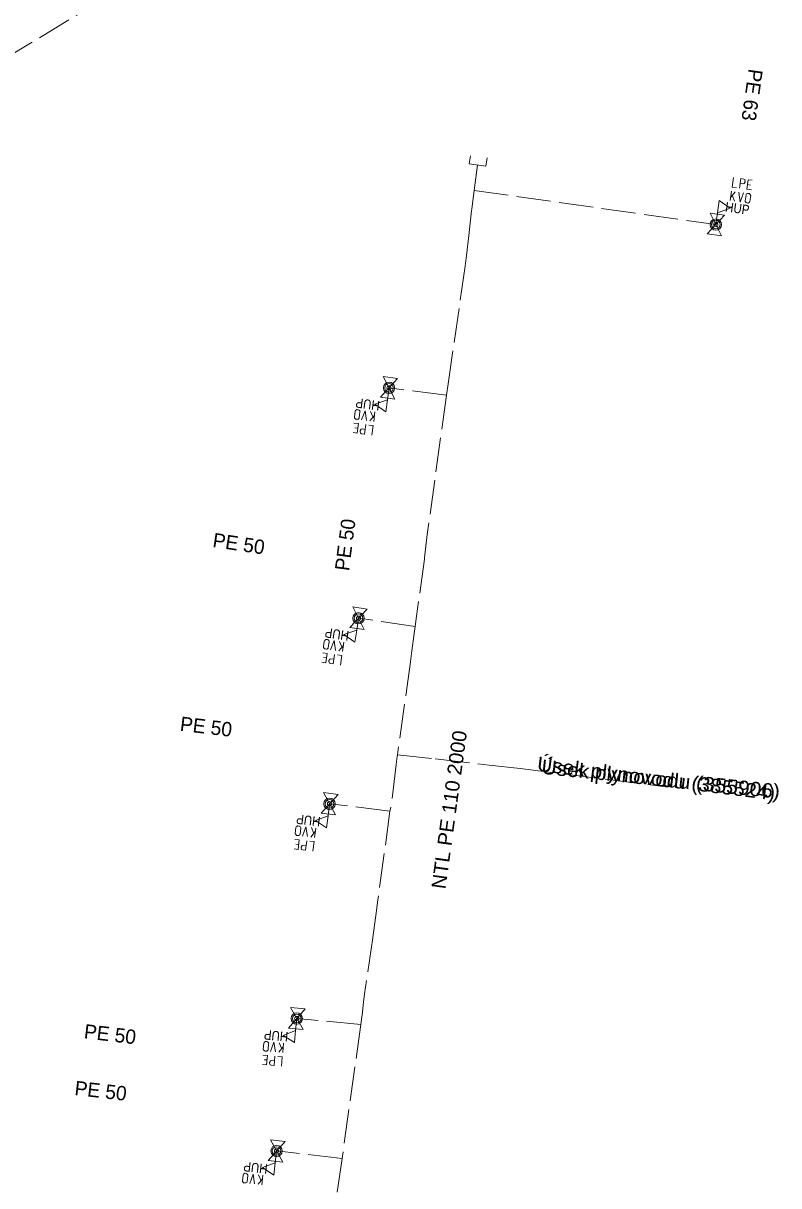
# Model space of a CAD drawing. Extents: x -688140 to -687678, y -1056859 to -1056384.
# Drawn here: x -687935 to -687895.3, y -1056552.8 to -1056491.8 of the extents above; entities that cross this region are included whole.
import ezdxf
from ezdxf.enums import TextEntityAlignment as Align

# ---------------------------------------------------------------- set-up
doc = ezdxf.new("R2010")
doc.units = 0
doc.header["$LTSCALE"] = 0.3
doc.linetypes.add('LONG_DASHED', pattern=[7.5, 6, -1.5])
for name, color, linetype, lineweight in [('12', 7, 'Continuous', 13), ('35', 7, 'LONG_DASHED', 13), ('50', 7, 'LONG_DASHED', 13)]:
    doc.layers.add(name, color=color, linetype=linetype, lineweight=lineweight)
doc.layers.add('15', color=7, linetype='Continuous')

msp = doc.modelspace()

# ---------------------------------------------------------------- linework, layer by layer
at = {"layer": '12'}
for p, q in [((-687897.187, -1056500.239), (-687897.345, -1056500.217)), ((-687896.802, -1056500.304), (-687896.96, -1056500.281)), ((-687897.797, -1056500.628), (-687897.867, -1056501.123)), ((-687897.84, -1056500.935), (-687897.599, -1056500.656)), ((-687897.766, -1056500.834), (-687897.639, -1056501.155)), ((-687897.081, -1056501.133), (-687897.037, -1056500.826)), ((-687896.79, -1056500.861), (-687896.833, -1056501.168)), ((-687898.163, -1056501.894), (-687899.077, -1056502.866)), ((-687898.925, -1056501.787), (-687898.315, -1056502.973)), ((-687898.925, -1056501.787), (-687898.163, -1056501.894)), ((-687898.62, -1056502.38), (-687898.532, -1056501.756)), ((-687899.077, -1056502.866), (-687898.315, -1056502.973)), ((-687916.222, -1056511.441), (-687915.318, -1056510.459)), ((-687915.318, -1056510.459), (-687916.082, -1056510.36)), ((-687915.458, -1056511.54), (-687916.082, -1056510.36)), ((-687915.77, -1056510.95), (-687915.851, -1056511.575)), ((-687915.458, -1056511.54), (-687916.222, -1056511.441)), ((-687917.583, -1056512.49), (-687917.543, -1056512.182)), ((-687917.295, -1056512.214), (-687917.335, -1056512.522)), ((-687916.533, -1056512.404), (-687916.771, -1056512.686)), ((-687916.607, -1056512.505), (-687916.737, -1056512.186)), ((-687916.573, -1056512.711), (-687916.509, -1056512.216)), ((-687917.564, -1056513.047), (-687917.406, -1056513.067)), ((-687917.179, -1056513.107), (-687917.02, -1056513.127)), ((-687917.831, -1056523.523), (-687916.909, -1056522.557)), ((-687916.909, -1056522.557), (-687917.671, -1056522.444)), ((-687917.069, -1056523.636), (-687917.671, -1056522.444)), ((-687917.069, -1056523.636), (-687917.831, -1056523.523)), ((-687917.37, -1056523.04), (-687917.462, -1056523.663)), ((-687919.211, -1056524.546), (-687919.165, -1056524.24)), ((-687918.918, -1056524.276), (-687918.963, -1056524.583)), ((-687918.16, -1056524.48), (-687918.403, -1056524.757)), ((-687918.235, -1056524.58), (-687918.359, -1056524.258)), ((-687918.205, -1056524.786), (-687918.132, -1056524.292)), ((-687919.202, -1056525.104), (-687919.044, -1056525.127)), ((-687918.818, -1056525.171), (-687918.66, -1056525.194)), ((-687919.337, -1056533.275), (-687918.443, -1056532.285)), ((-687918.443, -1056532.285), (-687919.207, -1056532.193)), ((-687918.573, -1056533.367), (-687919.207, -1056532.193)), ((-687918.573, -1056533.367), (-687919.337, -1056533.275)), ((-687918.89, -1056532.78), (-687918.965, -1056533.406)), ((-687920.688, -1056534.337), (-687920.651, -1056534.029)), ((-687920.403, -1056534.059), (-687920.44, -1056534.367)), ((-687919.639, -1056534.241), (-687919.875, -1056534.525)), ((-687919.712, -1056534.343), (-687919.845, -1056534.025)), ((-687919.676, -1056534.549), (-687919.617, -1056534.053)), ((-687920.664, -1056534.894), (-687920.505, -1056534.913)), ((-687920.278, -1056534.95), (-687920.119, -1056534.969)), ((-687921.043, -1056544.557), (-687920.177, -1056543.543)), ((-687920.177, -1056543.543), (-687920.943, -1056543.472)), ((-687920.277, -1056544.628), (-687920.943, -1056543.472)), ((-687920.61, -1056544.05), (-687920.668, -1056544.677)), ((-687920.277, -1056544.628), (-687921.043, -1056544.557)), ((-687922.365, -1056545.656), (-687922.336, -1056545.347)), ((-687922.087, -1056545.37), (-687922.116, -1056545.679)), ((-687921.319, -1056545.531), (-687921.547, -1056545.821)), ((-687921.389, -1056545.635), (-687921.531, -1056545.321)), ((-687921.348, -1056545.84), (-687921.302, -1056545.342)), ((-687922.326, -1056546.212), (-687922.166, -1056546.226)), ((-687921.938, -1056546.257), (-687921.779, -1056546.272)), ((-687921.226, -1056550.502), (-687921.991, -1056550.415)), ((-687921.349, -1056551.585), (-687921.991, -1056550.415)), ((-687922.114, -1056551.498), (-687921.226, -1056550.502)), ((-687921.67, -1056551), (-687921.741, -1056551.626)), ((-687921.349, -1056551.585), (-687922.114, -1056551.498)), ((-687923.458, -1056552.569), (-687923.423, -1056552.261)), ((-687923.175, -1056552.289), (-687923.21, -1056552.597)), ((-687922.482, -1056552.569), (-687922.617, -1056552.251)), ((-687922.445, -1056552.774), (-687922.388, -1056552.277)), ((-687922.41, -1056552.466), (-687922.644, -1056552.751))]:
    msp.add_line(p, q, dxfattribs=at)
for points in [[(-687910.624, -1056498.882), (-687910.683, -1056499.319), (-687911.557, -1056499.201), (-687911.498, -1056498.764)], [(-687897.696, -1056499.915), (-687897.766, -1056500.41), (-687897.539, -1056500.442)], [(-687897.38, -1056500.464), (-687897.31, -1056499.969), (-687897.152, -1056499.992)], [(-687897.152, -1056499.992), (-687897.105, -1056500.019), (-687897.077, -1056500.103), (-687897.082, -1056500.143), (-687897.134, -1056500.226), (-687897.187, -1056500.239)], [(-687896.706, -1056500.055), (-687896.924, -1056500.024), (-687896.994, -1056500.519), (-687896.756, -1056500.552)], [(-687897.421, -1056500.681), (-687897.352, -1056501.196), (-687897.163, -1056500.717)], [(-687897.037, -1056500.826), (-687897.033, -1056500.796), (-687897.009, -1056500.769), (-687896.965, -1056500.745), (-687896.926, -1056500.751), (-687896.876, -1056500.758), (-687896.846, -1056500.762), (-687896.812, -1056500.807), (-687896.795, -1056500.83), (-687896.79, -1056500.861)], [(-687897.081, -1056501.133), (-687897.086, -1056501.172), (-687897.069, -1056501.195), (-687897.034, -1056501.23), (-687896.996, -1056501.246), (-687896.946, -1056501.253), (-687896.916, -1056501.257), (-687896.871, -1056501.223), (-687896.849, -1056501.206), (-687896.833, -1056501.168)], [(-687917.335, -1056512.522), (-687917.339, -1056512.552), (-687917.363, -1056512.579), (-687917.406, -1056512.603), (-687917.446, -1056512.598), (-687917.495, -1056512.592), (-687917.525, -1056512.588), (-687917.56, -1056512.543), (-687917.577, -1056512.521), (-687917.583, -1056512.49)], [(-687917.295, -1056512.214), (-687917.29, -1056512.175), (-687917.307, -1056512.152), (-687917.343, -1056512.117), (-687917.381, -1056512.102), (-687917.431, -1056512.096), (-687917.461, -1056512.092), (-687917.506, -1056512.127), (-687917.528, -1056512.144), (-687917.543, -1056512.182)], [(-687916.95, -1056512.663), (-687917.024, -1056512.149), (-687917.208, -1056512.629)], [(-687917.657, -1056513.297), (-687917.439, -1056513.325), (-687917.375, -1056512.829), (-687917.613, -1056512.798)], [(-687917.211, -1056513.355), (-687917.258, -1056513.328), (-687917.287, -1056513.244), (-687917.282, -1056513.204), (-687917.231, -1056513.12), (-687917.179, -1056513.107)], [(-687916.988, -1056512.879), (-687917.052, -1056513.375), (-687917.211, -1056513.355)], [(-687916.666, -1056513.425), (-687916.601, -1056512.93), (-687916.829, -1056512.9)], [(-687918.918, -1056524.276), (-687918.912, -1056524.237), (-687918.929, -1056524.214), (-687918.964, -1056524.179), (-687919.002, -1056524.163), (-687919.052, -1056524.156), (-687919.081, -1056524.151), (-687919.127, -1056524.185), (-687919.149, -1056524.202), (-687919.165, -1056524.24)], [(-687918.581, -1056524.731), (-687918.646, -1056524.216), (-687918.838, -1056524.693)], [(-687918.963, -1056524.583), (-687918.968, -1056524.613), (-687918.992, -1056524.64), (-687919.036, -1056524.663), (-687919.075, -1056524.658), (-687919.125, -1056524.65), (-687919.155, -1056524.646), (-687919.188, -1056524.6), (-687919.205, -1056524.578), (-687919.211, -1056524.546)], [(-687919.3, -1056525.352), (-687919.082, -1056525.384), (-687919.009, -1056524.89), (-687919.246, -1056524.855)], [(-687918.855, -1056525.418), (-687918.901, -1056525.391), (-687918.929, -1056525.306), (-687918.923, -1056525.266), (-687918.87, -1056525.183), (-687918.818, -1056525.171)], [(-687918.623, -1056524.947), (-687918.696, -1056525.442), (-687918.855, -1056525.418)], [(-687918.311, -1056525.499), (-687918.237, -1056525.004), (-687918.465, -1056524.97)], [(-687920.403, -1056534.059), (-687920.398, -1056534.019), (-687920.416, -1056533.997), (-687920.452, -1056533.963), (-687920.49, -1056533.948), (-687920.54, -1056533.942), (-687920.57, -1056533.938), (-687920.614, -1056533.973), (-687920.637, -1056533.991), (-687920.651, -1056534.029)], [(-687920.44, -1056534.367), (-687920.443, -1056534.397), (-687920.467, -1056534.424), (-687920.51, -1056534.449), (-687920.55, -1056534.444), (-687920.6, -1056534.438), (-687920.629, -1056534.435), (-687920.664, -1056534.39), (-687920.682, -1056534.368), (-687920.688, -1056534.337)], [(-687920.053, -1056534.504), (-687920.133, -1056533.991), (-687920.312, -1056534.473)], [(-687920.755, -1056535.145), (-687920.536, -1056535.171), (-687920.477, -1056534.675), (-687920.715, -1056534.646)], [(-687920.308, -1056535.198), (-687920.355, -1056535.173), (-687920.385, -1056535.088), (-687920.381, -1056535.049), (-687920.33, -1056534.964), (-687920.278, -1056534.95)], [(-687920.09, -1056534.721), (-687920.149, -1056535.217), (-687920.308, -1056535.198)], [(-687919.762, -1056535.264), (-687919.702, -1056534.767), (-687919.931, -1056534.74)], [(-687922.087, -1056545.37), (-687922.084, -1056545.33), (-687922.102, -1056545.308), (-687922.139, -1056545.275), (-687922.178, -1056545.261), (-687922.228, -1056545.257), (-687922.258, -1056545.254), (-687922.301, -1056545.29), (-687922.323, -1056545.308), (-687922.336, -1056545.347)], [(-687921.726, -1056545.805), (-687921.819, -1056545.294), (-687921.985, -1056545.781)], [(-687922.409, -1056546.465), (-687922.19, -1056546.485), (-687922.144, -1056545.987), (-687922.383, -1056545.965)], [(-687922.116, -1056545.679), (-687922.119, -1056545.708), (-687922.141, -1056545.736), (-687922.184, -1056545.763), (-687922.224, -1056545.759), (-687922.274, -1056545.754), (-687922.303, -1056545.752), (-687922.34, -1056545.708), (-687922.358, -1056545.686), (-687922.365, -1056545.656)], [(-687921.756, -1056546.023), (-687921.802, -1056546.521), (-687921.961, -1056546.506)], [(-687921.414, -1056546.557), (-687921.368, -1056546.059), (-687921.597, -1056546.038)], [(-687921.961, -1056546.506), (-687922.009, -1056546.482), (-687922.042, -1056546.398), (-687922.038, -1056546.359), (-687921.99, -1056546.273), (-687921.938, -1056546.257)], [(-687923.175, -1056552.289), (-687923.17, -1056552.249), (-687923.188, -1056552.227), (-687923.224, -1056552.193), (-687923.263, -1056552.178), (-687923.313, -1056552.172), (-687923.342, -1056552.169), (-687923.387, -1056552.204), (-687923.409, -1056552.222), (-687923.423, -1056552.261)], [(-687922.822, -1056552.731), (-687922.905, -1056552.219), (-687923.081, -1056552.702)], [(-687923.21, -1056552.597), (-687923.213, -1056552.627), (-687923.236, -1056552.654), (-687923.279, -1056552.679), (-687923.319, -1056552.675), (-687923.369, -1056552.669), (-687923.399, -1056552.666), (-687923.434, -1056552.622), (-687923.452, -1056552.599), (-687923.458, -1056552.569)]]:
    msp.add_lwpolyline(points, dxfattribs=at)
for points in [[(-687898.532, -1056501.756), (-687897.863, -1056501.527), (-687898.443, -1056501.122)], [(-687915.851, -1056511.575), (-687916.517, -1056511.811), (-687915.933, -1056512.209)], [(-687917.462, -1056523.663), (-687918.132, -1056523.887), (-687917.556, -1056524.296)], [(-687918.965, -1056533.406), (-687919.629, -1056533.648), (-687919.041, -1056534.041)], [(-687920.668, -1056544.677), (-687921.325, -1056544.938), (-687920.727, -1056545.315)], [(-687921.741, -1056551.626), (-687922.403, -1056551.873), (-687921.813, -1056552.262)]]:
    msp.add_lwpolyline(points, close=True, dxfattribs=at)
for centre, radius in [((-687898.62, -1056502.38), 0.297), ((-687898.62, -1056502.38), 0.223), ((-687898.62, -1056502.38), 0.223), ((-687898.62, -1056502.38), 0.112), ((-687915.77, -1056510.95), 0.297), ((-687915.77, -1056510.95), 0.223), ((-687915.77, -1056510.95), 0.223), ((-687915.77, -1056510.95), 0.112), ((-687917.37, -1056523.04), 0.297), ((-687917.37, -1056523.04), 0.223), ((-687917.37, -1056523.04), 0.223), ((-687917.37, -1056523.04), 0.112), ((-687918.89, -1056532.78), 0.297), ((-687918.89, -1056532.78), 0.223), ((-687918.89, -1056532.78), 0.223), ((-687918.89, -1056532.78), 0.112), ((-687920.61, -1056544.05), 0.297), ((-687920.61, -1056544.05), 0.223), ((-687920.61, -1056544.05), 0.223), ((-687920.61, -1056544.05), 0.112), ((-687921.67, -1056551), 0.297), ((-687921.67, -1056551), 0.223), ((-687921.67, -1056551), 0.223), ((-687921.67, -1056551), 0.112)]:
    msp.add_circle(centre, radius, dxfattribs=at)
at = {"layer": '35'}
for points in [[(-687934.92, -1056483.379), (-687934.48, -1056484.1), (-687931.57, -1056488.93), (-687931.05, -1056489.78), (-687930.64, -1056490.47), (-687940.574, -1056496.498), (-687941.6, -1056497.12), (-687942.464, -1056497.696), (-687944.2, -1056498.69), (-687950.55, -1056502.49), (-687951.37, -1056502.98), (-687952.8, -1056503.81), (-687962, -1056509.53), (-687962.18, -1056509.64), (-687962.19, -1056509.625), (-687963.04, -1056508.39), (-687964.19, -1056506.75), (-687972.1, -1056511.04), (-687973.789, -1056512.111), (-687973.85, -1056512.15), (-687977.61, -1056514.19), (-687978.48, -1056514.66), (-687999.12, -1056527.17), (-688005.94, -1056531)], [(-687911.12, -1056499.26), (-687911.245, -1056500.184), (-687911.3, -1056500.59), (-687911.43, -1056501.55), (-687911.442, -1056501.661), (-687911.585, -1056502.962), (-687911.7, -1056504), (-687911.78, -1056504.57), (-687912.095, -1056506.783), (-687912.66, -1056510.74), (-687912.76, -1056511.34), (-687913.76, -1056518.65), (-687913.9, -1056519.87), (-687913.91, -1056519.941), (-687914.322, -1056522.924), (-687914.4, -1056523.48), (-687914.45, -1056523.84), (-687914.567, -1056524.751), (-687914.64, -1056525.31), (-687914.643, -1056525.328), (-687915.33, -1056530.21), (-687915.339, -1056530.3), (-687915.39, -1056530.72), (-687915.67, -1056532.98), (-687915.72, -1056533.16), (-687916.37, -1056537.94), (-687916.427, -1056538.374), (-687916.62, -1056539.8), (-687916.623, -1056539.823), (-687917.06, -1056542.76), (-687917.105, -1056543.189), (-687917.18, -1056543.87), (-687917.192, -1056543.953), (-687917.25, -1056544.36), (-687918.23, -1056551.39), (-687918.96, -1056556.31)]]:
    msp.add_lwpolyline(points, dxfattribs=at)
at = {"layer": '50'}
for p, q in [((-687911.3, -1056500.59), (-687898.62, -1056502.38)), ((-687912.76, -1056511.34), (-687915.77, -1056510.95)), ((-687914.4, -1056523.48), (-687917.37, -1056523.04)), ((-687915.72, -1056533.16), (-687918.89, -1056532.78)), ((-687917.25, -1056544.36), (-687920.61, -1056544.05)), ((-687918.23, -1056551.39), (-687921.67, -1056551))]:
    msp.add_line(p, q, dxfattribs=at)
msp.add_lwpolyline([(-687915.33, -1056530.21), (-687913.34, -1056530.42), (-687910.52, -1056530.75), (-687908.889, -1056530.929), (-687901.142, -1056531.901), (-687901.101, -1056531.507)], dxfattribs=at)

# ---------------------------------------------------------------- texts
at = {"layer": '12', "width": 0.9}
for rotation, p in [(351.967, (-687897.525, -1056501.777)), (172.615, (-687916.858, -1056511.565)), (171.572, (-687918.469, -1056523.635)), (173.165, (-687919.973, -1056533.405)), (174.729, (-687921.674, -1056544.705)), (173.532, (-687922.748, -1056551.632))]:
    msp.add_text('HUP', height=0.5, rotation=rotation, dxfattribs=at).set_placement(p, align=Align.CENTER)
at = {"layer": '15'}
for s, rotation, p in [('PE 63', 261.965, (-687896.896, -1056494.176)), ('PE 50', 82.617, (-687917.871, -1056520.587)), ('PE 50', 351.573, (-687925.058, -1056519.297)), ('PE 50', 353.164, (-687926.766, -1056528.941)), ('PE 50', 353.21, (-687931.805, -1056545.082)), ('PE 50', 353.532, (-687932.296, -1056548.06))]:
    msp.add_text(s, height=0.75, rotation=rotation, dxfattribs=at).set_placement(p)
for s, rotation, width, p in [('NTL PE 110 2000', 82.21, 1.05, (-687912.806, -1056537.286)), ('Úsek plynovodu (385524)', 352.857, 1.1, (-687908.03, -1056531.04)), ('Úsek plynovodu (355906)', 353.998, 1.1, (-687907.8, -1056531.2))]:
    msp.add_text(s, height=0.75, rotation=rotation, dxfattribs=dict(at, width=width)).set_placement(p)

doc.saveas('drawing.dxf')
